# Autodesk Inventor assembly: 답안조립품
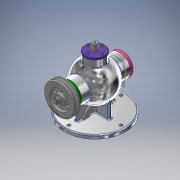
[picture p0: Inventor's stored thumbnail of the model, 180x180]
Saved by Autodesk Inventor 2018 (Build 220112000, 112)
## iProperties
Created: 2020-08
Part Number: 답안조립품
Material: 일반
Document SubType Name: Assembly
Designer: USER
Author: USER
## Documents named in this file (18)
- C:\Users\USER\Desktop\700806V1049\답안조립품.iam
- C:\Users\USER\Desktop\700806V1049\본체.ipt
- C:\Users\USER\Desktop\700806V1049\뒤커버.ipt
- C:\Users\USER\Desktop\700806V1049\베어링 6202.ipt
- 베어링 6202.ipt
- C:\Users\USER\Desktop\700806V1049\멈춤링 15x1.ipt
- C:\Users\USER\Desktop\700806V1049\멈춤링 35x1.6.ipt
- 멈춤링 35x1.6.ipt
- C:\Users\USER\Desktop\700806V1049\편심축.ipt
- C:\Users\USER\Desktop\700806V1049\슬라이드.ipt
- C:\Users\USER\Desktop\700806V1049\상부커버.ipt
- C:\Users\USER\Desktop\700806V1049\칼라.ipt
- C:\Users\USER\Desktop\700806V1049\앞커버.ipt
- C:\Users\USER\Desktop\700806V1049\오일 실 15 30 7.ipt
- C:\Users\USER\Desktop\700806V1049\Ű 3x3x12.ipt
- C:\Users\USER\Desktop\700806V1049\V-벨트풀리.ipt
- C:\Users\USER\Desktop\700806V1049\너트 M8.ipt
- C:\Users\USER\Desktop\700806V1049\볼트 M4.ipt
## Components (3 placed, 2 different names)
1. Ű 3x3x12:1
2. V-벨트풀리:1
3. V-벨트풀리:2
